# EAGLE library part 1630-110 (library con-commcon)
COMPACT PCI TYPE B - 110 PINS 2mm HARD METRIC SOCKETS
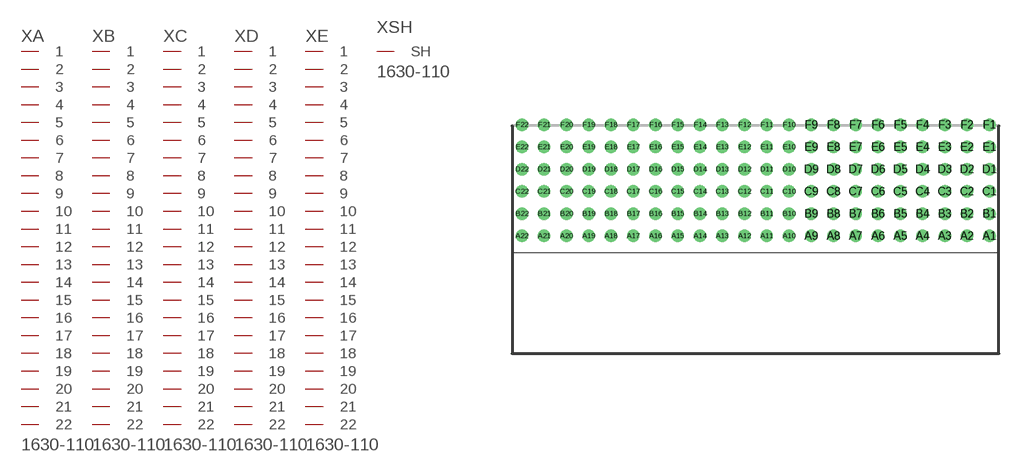
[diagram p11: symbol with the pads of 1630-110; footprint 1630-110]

Designator prefix X; gates A=PIN22 B=PIN22 C=PIN22 D=PIN22 E=PIN22 SH=SHIELD

## 1630-110 (MPN: 16-301-1-01; OC_FARNELL: unknown; OC_NEWARK: 97M8043)  [1630-110]
A1  A:1  pas
A2  A:2  pas
A3  A:3  pas
A4  A:4  pas
A5  A:5  pas
A6  A:6  pas
A7  A:7  pas
A8  A:8  pas
A9  A:9  pas
A10  A:10  pas
A11  A:11  pas
A12  A:12  pas
A13  A:13  pas
A14  A:14  pas
A15  A:15  pas
A16  A:16  pas
A17  A:17  pas
A18  A:18  pas
A19  A:19  pas
A20  A:20  pas
A21  A:21  pas
A22  A:22  pas
B1  B:1  pas
B2  B:2  pas
B3  B:3  pas
B4  B:4  pas
B5  B:5  pas
B6  B:6  pas
B7  B:7  pas
B8  B:8  pas
B9  B:9  pas
B10  B:10  pas
B11  B:11  pas
B12  B:12  pas
B13  B:13  pas
B14  B:14  pas
B15  B:15  pas
B16  B:16  pas
B17  B:17  pas
B18  B:18  pas
B19  B:19  pas
B20  B:20  pas
B21  B:21  pas
B22  B:22  pas
C1  C:1  pas
C2  C:2  pas
C3  C:3  pas
C4  C:4  pas
C5  C:5  pas
C6  C:6  pas
C7  C:7  pas
C8  C:8  pas
C9  C:9  pas
C10  C:10  pas
C11  C:11  pas
C12  C:12  pas
C13  C:13  pas
C14  C:14  pas
C15  C:15  pas
C16  C:16  pas
C17  C:17  pas
C18  C:18  pas
C19  C:19  pas
C20  C:20  pas
C21  C:21  pas
C22  C:22  pas
D1  D:1  pas
D2  D:2  pas
D3  D:3  pas
D4  D:4  pas
D5  D:5  pas
D6  D:6  pas
D7  D:7  pas
D8  D:8  pas
D9  D:9  pas
D10  D:10  pas
D11  D:11  pas
D12  D:12  pas
D13  D:13  pas
D14  D:14  pas
D15  D:15  pas
D16  D:16  pas
D17  D:17  pas
D18  D:18  pas
D19  D:19  pas
D20  D:20  pas
D21  D:21  pas
D22  D:22  pas
E1  E:1  pas
E2  E:2  pas
E3  E:3  pas
E4  E:4  pas
E5  E:5  pas
E6  E:6  pas
E7  E:7  pas
E8  E:8  pas
E9  E:9  pas
E10  E:10  pas
E11  E:11  pas
E12  E:12  pas
E13  E:13  pas
E14  E:14  pas
E15  E:15  pas
E16  E:16  pas
E17  E:17  pas
E18  E:18  pas
E19  E:19  pas
E20  E:20  pas
E21  E:21  pas
E22  E:22  pas
F1  SH:SH  pas

## Footprint 1630-110 (pad centres in mm)
COMPACT PCI TYPE B - 110 PINS 2mm HARD METRIC SOCKETS
drill 0.6 round: A1 21,1.27; A2 19,1.27; A3 17,1.27; A4 15,1.27; A5 13,1.27; A6 11,1.27; A7 9,1.27; A8 7,1.27; A9 5,1.27; A10 3,1.27; A11 1,1.27; A12 -1,1.27; A13 -3,1.27; A14 -5,1.27; A15 -7,1.27; A16 -9,1.27; A17 -11,1.27; A18 -13,1.27; A19 -15,1.27; A20 -17,1.27; A21 -19,1.27; A22 -21,1.27; B1 21,3.27; B2 19,3.27; B3 17,3.27; B4 15,3.27; B5 13,3.27; B6 11,3.27; B7 9,3.27; B8 7,3.27; B9 5,3.27; B10 3,3.27; B11 1,3.27; B12 -1,3.27; B13 -3,3.27; B14 -5,3.27; B15 -7,3.27; B16 -9,3.27; B17 -11,3.27; B18 -13,3.27; B19 -15,3.27; B20 -17,3.27; B21 -19,3.27; B22 -21,3.27; C1 21,5.27; C2 19,5.27; C3 17,5.27; C4 15,5.27; C5 13,5.27; C6 11,5.27; C7 9,5.27; C8 7,5.27; C9 5,5.27; C10 3,5.27; C11 1,5.27; C12 -1,5.27; C13 -3,5.27; C14 -5,5.27; C15 -7,5.27; C16 -9,5.27; C17 -11,5.27; C18 -13,5.27; C19 -15,5.27; C20 -17,5.27; C21 -19,5.27; C22 -21,5.27; D1 21,7.27; D2 19,7.27; D3 17,7.27; D4 15,7.27; D5 13,7.27; D6 11,7.27; D7 9,7.27; D8 7,7.27; D9 5,7.27; D10 3,7.27; D11 1,7.27; D12 -1,7.27; D13 -3,7.27; D14 -5,7.27; D15 -7,7.27; D16 -9,7.27; D17 -11,7.27; D18 -13,7.27; D19 -15,7.27; D20 -17,7.27; D21 -19,7.27; D22 -21,7.27; E1 21,9.27; E2 19,9.27; E3 17,9.27; E4 15,9.27; E5 13,9.27; E6 11,9.27; E7 9,9.27; E8 7,9.27; E9 5,9.27; E10 3,9.27; E11 1,9.27; E12 -1,9.27; E13 -3,9.27; E14 -5,9.27; E15 -7,9.27; E16 -9,9.27; E17 -11,9.27; E18 -13,9.27; E19 -15,9.27; E20 -17,9.27; E21 -19,9.27; E22 -21,9.27; F1 21,11.27; F2 19,11.27; F3 17,11.27; F4 15,11.27; F5 13,11.27; F6 11,11.27; F7 9,11.27; F8 7,11.27; F9 5,11.27; F10 3,11.27; F11 1,11.27; F12 -1,11.27; F13 -3,11.27; F14 -5,11.27; F15 -7,11.27; F16 -9,11.27; F17 -11,11.27; F18 -13,11.27; F19 -15,11.27; F20 -17,11.27; F21 -19,11.27; F22 -21,11.27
